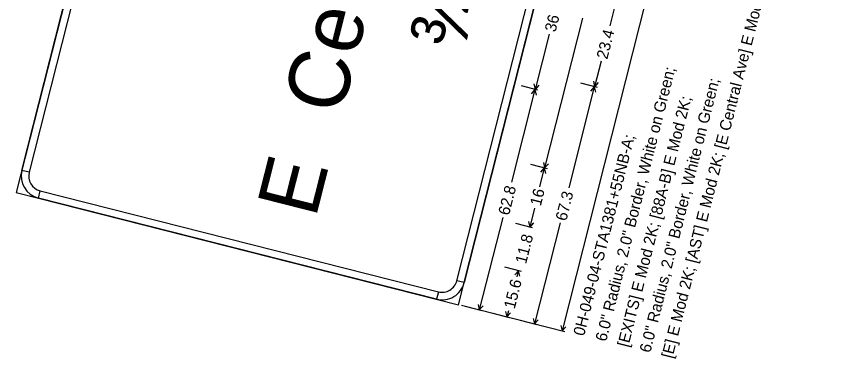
# Model space of a CAD drawing. Extents: x 670006 to 670131, y 737844 to 738002.
# Drawn here: x 670010.88 to 670044.77, y 737852.53 to 737866.83 of the extents above; entities that cross this region are included whole.
import ezdxf

# ---------------------------------------------------------------- set-up
doc = ezdxf.new("R2010")
doc.units = 0
doc.layers.add('R_SIGN', color=7, linetype='Continuous')

msp = doc.modelspace()

# ---------------------------------------------------------------- linework, layer by layer
at = {"layer": 'R_SIGN'}
for p, q in [((670018.845, 737890.875), (670010.88, 737859.469)), ((670029.354, 737854.784), (670037.319, 737886.19)), ((670037.492, 737868.748), (670033.673, 737853.688)), ((670035.676, 737866.42), (670035.945, 737867.483)), ((670034.532, 737866.742), (670032.947, 737860.492)), ((670033.139, 737866.082), (670032.552, 737863.769)), ((670035.302, 737864.948), (670035.033, 737863.885)), ((670032.667, 737863.74), (670031.976, 737863.915)), ((670032.501, 737864.002), (670032.552, 737863.769)), ((670032.707, 737863.949), (670032.552, 737863.769)), ((670033.964, 737859.669), (670035.033, 737863.885)), ((670035.148, 737863.856), (670034.457, 737864.031)), ((670034.878, 737863.705), (670035.033, 737863.885)), ((670034.982, 737864.117), (670035.033, 737863.885)), ((670035.188, 737864.065), (670035.033, 737863.885)), ((670035.084, 737863.653), (670035.033, 737863.885)), ((670031.571, 737859.902), (670032.552, 737863.769)), ((670032.397, 737863.59), (670032.552, 737863.769)), ((670032.603, 737863.537), (670032.552, 737863.769)), ((670033.062, 737860.463), (670032.371, 737860.638)), ((670032.746, 737859.699), (670032.947, 737860.492)), ((670032.791, 737860.312), (670032.947, 737860.492)), ((670032.896, 737860.724), (670032.947, 737860.492)), ((670033.102, 737860.672), (670032.947, 737860.492)), ((670032.998, 737860.26), (670032.947, 737860.492)), ((670011.422, 737860.315), (670011.114, 737860.393)), ((670010.88, 737859.469), (670029.354, 737854.784)), ((670011.804, 737859.235), (670011.882, 737859.543)), ((670032.523, 737858.822), (670032.322, 737858.029)), ((670031.199, 737858.432), (670030.218, 737854.565)), ((670032.437, 737858), (670031.746, 737858.175)), ((670032.271, 737858.261), (670032.322, 737858.029)), ((670032.477, 737858.209), (670032.322, 737858.029)), ((670033.59, 737858.197), (670032.521, 737853.981)), ((670031.975, 737856.177), (670031.284, 737856.352)), ((670031.704, 737856.026), (670031.86, 737856.206)), ((670031.796, 737855.955), (670031.86, 737856.206)), ((670031.911, 737855.974), (670031.86, 737856.206)), ((670029.588, 737855.707), (670029.28, 737855.786)), ((670028.508, 737855.326), (670028.43, 737855.018)), ((670029.354, 737854.784), (670029.354, 737854.784)), ((670033.788, 737853.659), (670029.469, 737854.755)), ((670030.333, 737854.536), (670029.642, 737854.711)), ((670030.167, 737854.797), (670030.218, 737854.565)), ((670030.373, 737854.745), (670030.218, 737854.565)), ((670031.485, 737854.243), (670030.793, 737854.419)), ((670031.318, 737854.505), (670031.369, 737854.273)), ((670031.433, 737854.524), (670031.369, 737854.273)), ((670031.525, 737854.452), (670031.369, 737854.273)), ((670032.636, 737853.951), (670031.945, 737854.127)), ((670032.47, 737854.213), (670032.521, 737853.981)), ((670032.676, 737854.16), (670032.521, 737853.981)), ((670033.622, 737853.921), (670033.673, 737853.688)), ((670033.828, 737853.868), (670033.673, 737853.688))]:
    msp.add_line(p, q, dxfattribs=at)
for points in [[(670018.919, 737889.873), (670011.422, 737860.315), (670011.114, 737860.393), (670018.611, 737889.951), (670018.919, 737889.873)], [(670029.28, 737855.786), (670036.777, 737885.344), (670037.085, 737885.266), (670029.588, 737855.707), (670029.28, 737855.786)], [(670011.882, 737859.543), (670028.508, 737855.326), (670028.43, 737855.018), (670011.804, 737859.235), (670011.882, 737859.543)]]:
    msp.add_lwpolyline(points, close=True, dxfattribs=at)
for centre, radius, start, end in [((670012.038, 737860.159), 0.953, 165.7688, 255.7684), ((670012.038, 737860.159), 0.635, 165.7688, 255.7684), ((670028.665, 737855.942), 0.953, 255.7684, 345.7686), ((670028.665, 737855.942), 0.635, 255.7684, 345.7686)]:
    msp.add_arc(centre, radius, start, end, dxfattribs=at)

# ---------------------------------------------------------------- texts
for s, height, p in [('[E] E Mod 2K; [AST] E Mod 2K; [E Central Ave] E Mod 2K; [3/4] E Mod 2K; [MILE] E Mod 2K; ', 0.47522, (670038.279, 737852.52)), ('¾', 2.382, (670029.557, 737865.274)), ('e', 2.541, (670025.09, 737865.106)), ('36', 0.4752, (670033.398, 737866.138)), ('23.4', 0.4752, (670035.562, 737865.004)), ('C', 2.541, (670024.466, 737862.643)), ('6.0" Radius, 2.0" Border, White on Green; ', 0.47522, (670035.515, 737853.221)), ('6.0" Radius, 2.0" Border, White on Green; ', 0.47522, (670037.358, 737852.754)), ('[EXITS] E Mod 2K; [88A-B] E Mod 2K; ', 0.47522, (670036.436, 737852.988)), ('0H-049-04-STA1381+55NB-A; ', 0.47522, (670034.594, 737853.455)), ('E', 2.541, (670023.379, 737858.357)), ('62.8', 0.4752, (670031.458, 737858.489)), ('16', 0.4752, (670032.783, 737858.879)), ('67.3', 0.4752, (670033.85, 737858.253)), ('11.8', 0.4752, (670032.17, 737856.461)), ('15.6', 0.4752, (670031.693, 737854.58))]:
    msp.add_text(s, height=height, rotation=75.7686, dxfattribs=at).set_placement(p)

doc.saveas('drawing.dxf')
